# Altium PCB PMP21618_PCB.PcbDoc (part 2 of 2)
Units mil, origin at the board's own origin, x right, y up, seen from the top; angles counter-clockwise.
Board outline 4330 x 1770 mil, 4 copper layers (Top Layer, Signal Layer 1, Signal Layer 2, Bottom Layer), stack 136.834 mil thick; 75 components, 40 nets, 205 pads, 71 vias.
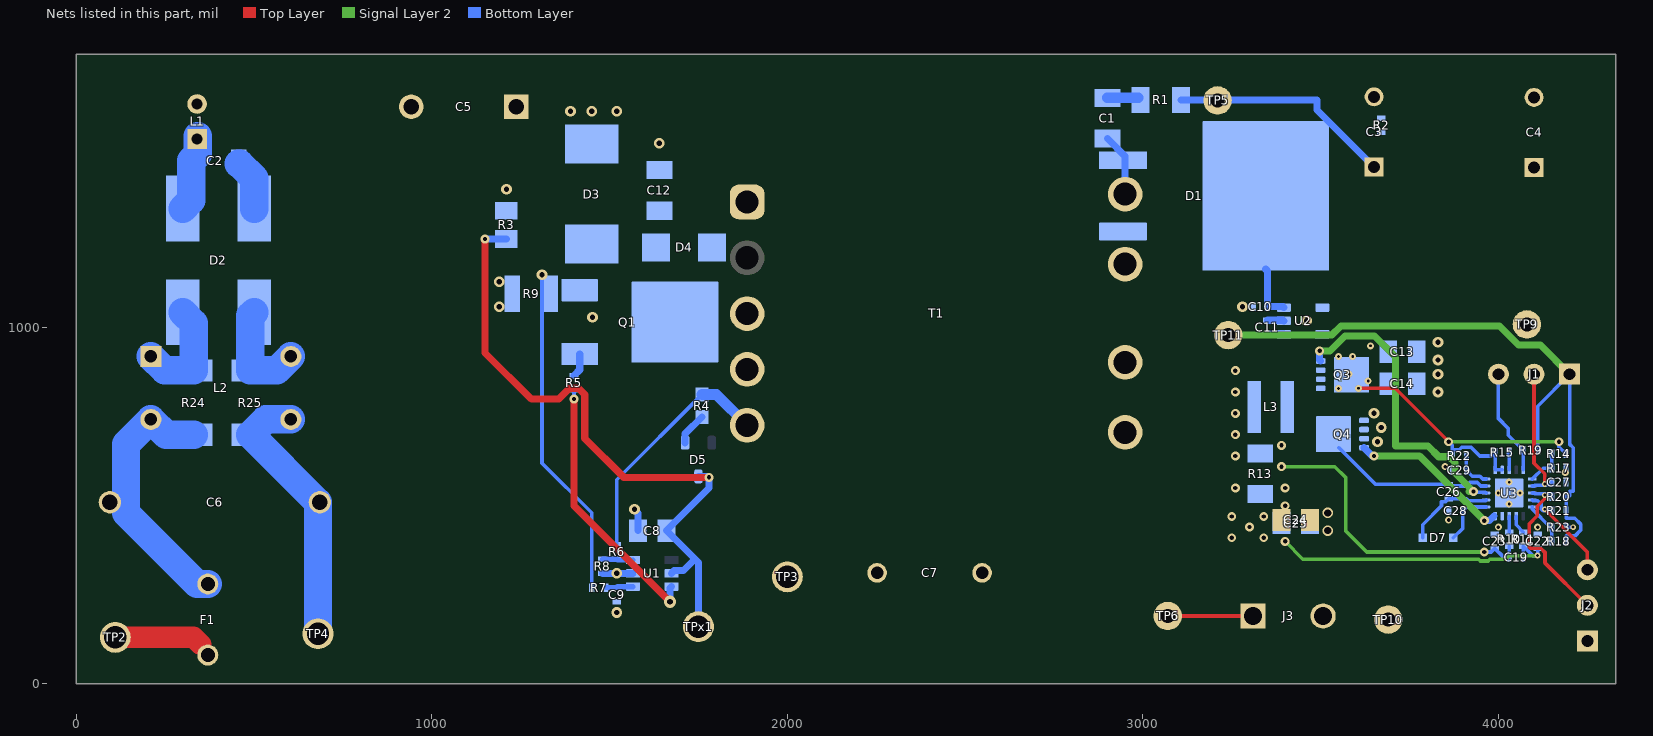
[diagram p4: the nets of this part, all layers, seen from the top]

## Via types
v1: diameter 25, hole 12, Top Layer to Bottom Layer, 26 vias
v2: diameter 30, hole 15, Top Layer to Bottom Layer, 21 vias
v3: diameter 19.68, hole 7.87, Top Layer to Bottom Layer, 10 vias
v4: diameter 16, hole 8, Top Layer to Bottom Layer, 5 vias
v5: diameter 20, hole 10, Top Layer to Bottom Layer, 5 vias
v6: diameter 30, hole 20, Top Layer to Bottom Layer, 2 vias
v7: diameter 34, hole 16, Top Layer to Bottom Layer, 1 vias
v8: diameter 19.68, hole 7.87, Top Layer to Bottom Layer, tented both sides, 1 vias

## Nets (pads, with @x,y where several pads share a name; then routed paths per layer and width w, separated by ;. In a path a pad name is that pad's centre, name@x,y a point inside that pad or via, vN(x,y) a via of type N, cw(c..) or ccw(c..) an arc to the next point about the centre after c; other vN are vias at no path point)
3v3: C11.1 J1.1 R18.2 R19.1 R20.1 R21.1 TP11.1 U2.1 | length 1991.7
  Signal Layer 2 w20: TP11.1@3240,980 3531.38,980 3556.97,1005.59 4002.56,1005.59 4056.03,952.13 4117.87,952.13 J1.1@4200,870
  Bottom Layer w10: TP11.1@3240,980 3348.5,980 C11.1@3350.31,981.81 ; R19.1@4110.16,655.91 4110.16,780.16 J1.1@4200,870 4200,673.77 4210.53,663.24 4210.53,603.81 4210.75,603.59 4210.75,541.25 4210.53,541.03 4200,541.03 4200,528.19 4197.72,525.91 R20.1@4190.16,525.91 R21.1@4190.16,485.91 4190.16,464.87 4214.65,464.87 4230.87,448.65 4230.87,430.87 4215.13,415.13 4190.16,415.13 4190.16,400.16 R18.2@4190,400
  Bottom Layer w20: C11.1@3350.31,981.81 3351.1,982.6 U2.1@3396.18,982.6
16VOUT: C3.1 C4.1 C10.1 C13.2 C14.2 D1.2 Q3.5 Q3.6 Q3.7 Q3.8 Q3.9 R1.2 R2.2 R14.2 R15.2 R22.1 TP5.1 U2.3 U3.1 U3.2 | length 1687.4
  Top Layer w10: v3(3606.29,830.31) 3709.69,830.31 v1(3860,680)
  Signal Layer 2 w10: v1(3860,680) v1(4170,680)
  Bottom Layer w10: v1(3860,680) 3870,670 3870,659.63 ; R22.1@3870,640 3870,659.63 ; U3.2@4010.47,600.87 U3.1@3990.79,600.87 3990.79,649.21 R15.2@3990,650 3980,640 3947.71,640 3922.83,664.87 3897.17,664.87 3889.63,657.33 3872.29,657.33 3870,659.63 ; v1(4170,680) 4170,666.06 R14.2@4190.16,645.91
  Bottom Layer w20: R1.2@3107.09,1641.49 3208.51,1641.49 TP5.1@3210,1640 3211.49,1641.49 3490,1641.49 3490,1613.07 C3.1@3631.57,1471.49 ; D1.2@3345.51,1165.23 3350,1160.74 C10.1@3350,1060 3393.58,1060 U2.3@3396.18,1057.4
  other v3: 3550,830 3633.7,851.21 3580,870 3550,920 3590,920
  other v8: 3640,950
ACOK: J1.3 R19.2 U3.5 | length 298.5
  Bottom Layer w10: J1.3@4000,870 4000,745.28 4027.87,717.4 4027.87,698.19 R19.2@4070.16,655.91 4069.53,655.28 U3.5@4069.53,600.87
GND: C3.2 C4.2 C7.1 C10.2 C11.2 C13.1 C14.1 C22.1 C23.1 C24.1 C25.1 C27.2 C28.2 C29.2 J2.1 J3.2 Q4.1 Q4.2 Q4.3 R2.1 R17.1 R23.1 T1.6 T1.7 TP9.1 TP10.1 U2.2 U2.4 U2.5 U3.14 U3.21 | length 59
  Bottom Layer w10: R23.1@4190,440 v4@4202.43,440
  Bottom Layer w20: C11.2@3350.31,1021.81 3394.37,1021.81 U2.2@3396.18,1020
  other v2: 3660,680 3670,720 3650,760 3830,820 3830,870 3830,910 3830,960 3460,1020 3280,1060
  other v3: 4030.16,505.39 3999.65,535.91 4060.67,535.91 4030.16,566.42
  other v4: 4210,440
  other v5: 4000,440 4110,440 3860,460 4187.87,594.11 3850,610
  other v6: 3520,430 3520,480
HIDRV: Q3.4 U3.18 | length 879
  Signal Layer 2 w20: v1(3497.04,935.63) 3526.43,935.63 3568.52,977.72 3651.48,977.72 3710,919.2 3710,667.87 3802.13,667.87 3832.13,637.87 3861.55,637.87 3877.87,621.55 3877.87,592.13 v1(3930,540) v1@3917.84,540
  Bottom Layer w10: v1(3930,540) 3932.28,537.72 3963.39,537.72 U3.18@3965.2,535.91
  Bottom Layer w20: Q3.4@3500,907.24 3497.04,910.19 v1(3497.04,935.63) v1@3500,932.67
IOUT: C27.1 J1.2 U3.7 | length 390.3
  Top Layer w10: J1.2@4100,870 4100,620 4130,590 v4(4130,561.2)
  Bottom Layer w10: U3.7@4095.12,555.59 4100.71,555.59 4102.8,557.68 v4@4126.48,557.68 ; v4(4130,561.2) v4@4126.48,557.68 ; C27.1@4150.16,565.91 4150.16,557.68 v4@4126.48,557.68
NetC1_1: C1.1 R1.1 | length 95.2
  Bottom Layer w10: R1.1@2987.32,1647.09 R1.1@2992.91,1641.49
  Bottom Layer w30: C1.1@2900,1647.09 R1.1@2987.32,1647.09
NetC1_2: C1.2 D1.1 D1.3 T1.8 T1.9 | length 177.1
  Bottom Layer w20: C1.2@2900,1532.91 2950,1482.92 T1.9@2950,1376.49
NetC2_1: C2.1 D2.1 L1.1 | length 221.7
  Bottom Layer w80: D2.1@299.61,1335.67 323.07,1359.13 C2.1@323.07,1470 341.57,1488.5 L1.1@341.57,1540
NetC5_1: C5.1 C12.1 D3.2 L1.2 R3.2 T1.1
  other v2: 1210,1390 1640,1520 1390,1610 1450,1610 1520,1610
NetC6_1: C6.1 F1.1 L2.2 R24.1 | length 742.6
  Bottom Layer w80: R24.1@330,699.45 253.39,699.45 L2.2@210,742.83 140,672.83 140,480 340,280 F1.1@370,280
NetC6_2: C6.2 L2.3 R25.1 TP4.1 | length 769.8
  Bottom Layer w80: L2.3@603.7,742.83 533.39,742.83 R25.1@490,699.45 680,509.45 TP4.1@680,140
NetC8_1: C8.1 D5.3 R3.1 TPx1.1 U1.2 | length 1872.7
  Top Layer w20: v1(1150,1250) 1150,930 1280,800 1357.04,800 1387.42,830.37 1412.58,830.37 1430.37,812.58 1430.37,689.63 1540,580 v1(1780,580)
  Bottom Layer w20: v1(1150,1250) R3.1@1210,1250 ; U1.2@1674.13,310 1681.85,317.72 1707.72,317.72 1740,350 ; TPx1.1@1750,160 1750,340 1740,350 ; D5.3@1750,582.76 1777.24,582.76 v1(1780,580) 1780,550 C8.1@1660,430 1740,350
NetC9_1: C9.1 R7.1 U1.4 | length 76.9
  Bottom Layer w15: R7.1@1490,270 C9.1@1520,270 1522.6,272.6 U1.4@1565.87,272.6
NetC12_2: C12.2 D3.1 D4.1
NetC19_1: C19.1 C22.2 C24.2 C25.2 J3.1 R11.2 R13.2 TP6.1 | length 1079.9
  Top Layer w10: TP6.1@3070,190 J3.1@3310,190
  Signal Layer 2 w10: v1(3400,400) 3450,350 3944.12,350 3949.49,344.63 3970.51,344.63 3975.88,350 4020,350 4030,360 v4(4110,360)
  Bottom Layer w10: C19.1@4070.16,355.91 R11.2@4070.16,385.91 4096.06,360 v4(4110,360) C22.2@4110,380
  other v1: 3250,410 3340,410 3300,440 3250,470 3340,470 3400,500 3260,550 3400,550
NetC19_2: C19.2 C23.2 L3.2 R10.2 R13.1 | length 871.6
  Signal Layer 2 w10: v1(3390,610) 3540,610 3570,580 3570,430 3630,370 v1(3960,370)
  Bottom Layer w10: v1(3960,370) 3980,370 C23.2@3990,380 4014.09,355.91 C19.2@4030.16,355.91 R10.2@4030.16,385.91
  other v1: 3260,640 3390,670 3260,700 3260,760 3260,820 3260,880
NetC26_1: C26.1 L3.1 Q3.1 Q3.2 Q3.3 Q4.5 Q4.6 Q4.7 Q4.8 Q4.9 U3.19 | length 466.5
  Bottom Layer w10: Q4.9@3551.38,663.23 3654.61,560 C26.1@3860,560 3864.41,555.59 3909.71,555.59 3919.49,565.37 3940.51,565.37 3950.29,555.59 U3.19@3965.2,555.59
NetC26_2: C26.2 D7.1 U3.17 | length 254.9
  Bottom Layer w10: D7.1@3786.69,410 3786.69,446.69 3839.78,499.78 3839.78,510.78 3850.78,510.78 C26.2@3860,520 3910,520 3915.37,514.63 3963.6,514.63 U3.17@3965.2,516.22
NetC28_1: C28.1 D7.2 U3.16 | length 156.5
  Bottom Layer w10: D7.2@3873.31,410 3900.16,436.85 C28.1@3900.16,485.91 3910.79,496.54 U3.16@3965.2,496.54
NetC29_1: C29.1 R22.2 U3.20 | length 105.4
  Bottom Layer w10: R22.2@3910,640 C29.1@3910,600 3926.75,583.25 3947.91,583.25 3955.89,575.28 U3.20@3965.2,575.28
NetD2_2: D2.2 L2.1 R24.2 | length 312.7
  Bottom Layer w80: L2.1@210,920 249.45,880.55 R24.2@330,880.55 330,1013.94 D2.2@299.61,1044.33
NetD2_3: D2.3 L2.4 R25.2 | length 298.1
  Bottom Layer w80: D2.3@500.39,1044.33 490,1033.94 R25.2@490,880.55 564.25,880.55 L2.4@603.7,920
NetD4_2: D4.2 Q1.2 T1.3
NetD5_1: D5.1 R4.1 | length 92.4
  Bottom Layer w20: D5.1@1712.6,677.24 1712.6,702.6 R4.1@1760,750
NetF1_2: F1.2 TP2.1 | length 248.3
  Top Layer w60: TP2.1@110,130 330,130 350,110
NetQ1_1: Q1.1 R5.2 | length 66.9
  Bottom Layer w20: R5.2@1400,866.49 1416.14,882.63 Q1.1@1416.14,926.73
NetQ1_3: Q1.3 R7.2 R9.2 | length 937.6
  Bottom Layer w10: v2(1310,1149.64) 1310,620 1450,480 R7.2@1450,270
  other v2: 1452.2,1030
NetQ4_4: Q4.4 U3.15 | length 456
  Signal Layer 2 w20: v1(3650,640) 3778.43,640 v1(3960.28,458.15)
  Bottom Layer w20: Q4.4@3622.05,663.07 3645.12,640 v1(3650,640) ; v1(3960.28,458.15) 3975.08,458.15 U3.15@3987.87,470.94
NetR4_2: R4.2 R6.2 T1.5 | length 685.2
  Bottom Layer w10: R6.2@1520,390 1520,572.99 R4.2@1760,812.99
  Bottom Layer w30: R4.2@1760,812.99 1800.5,812.99 T1.5@1887,726.49
NetR5_1: R5.1 U1.3 | length 752.6
  Top Layer w20: v1(1400,800) 1400,500 v7(1670,230)
  Bottom Layer w10: v1(1400,800) R5.1@1400,826.49
  Bottom Layer w20: v7(1670,230) 1670,268.46 U1.3@1674.13,272.6
NetR6_1: R6.1 R8.2 U1.6 | length 86.9
  Bottom Layer w15: R8.2@1480,350 R6.1@1520,350 1522.6,347.4 U1.6@1565.87,347.4
NetR10_1: R10.1 U3.13 | length 45
  Bottom Layer w10: R10.1@4030.16,425.91 U3.13@4030.16,470.94
NetR11_1: R11.1 U3.12 | length 53.5
  Bottom Layer w10: U3.12@4049.84,470.94 4049.84,446.22 R11.1@4070.16,425.91
NetR14_1: R14.1 R17.2 U3.6 | length 107.7
  Bottom Layer w10: U3.6@4095.12,575.28 4125.75,605.91 R17.2@4150.16,605.91 R14.1@4150.16,645.91
NetR15_1: R15.1 U3.3 | length 49.2
  Bottom Layer w10: R15.1@4030,650 4030.16,649.84 U3.3@4030.16,600.87
NetR18_1: R18.1 R23.2 U3.10 | length 121.6
  Bottom Layer w10: U3.10@4095.12,496.54 4095.12,490.94 4146.06,440 R23.2@4150,440 R18.1@4150,400
PGND: C2.2 C5.2 C7.2 C8.2 C9.2 D2.4 R8.1 R9.1 T1.4 TP3.1 U1.5 | length 295.9
  Bottom Layer w20: R8.1@1480,310 v2(1520,310) U1.5@1565.87,310 ; v2(1570,490) 1580,480 C8.2@1580,430
  Bottom Layer w80: C2.2@456.93,1462.13 459.37,1462.13 500.39,1421.1 D2.4@500.39,1335.67
  other v2: 1520,200 1190,1060 1190,1130
SCL: J2.3 R21.2 U3.9 | length 295.4
  Top Layer w10: v4(4130,490) 4250,370 J2.3@4250,320
  Bottom Layer w10: U3.9@4095.12,516.22 4096.93,514.41 4110.82,514.41 4119.8,505.43 4119.8,491.54 4125.43,485.91 R21.2@4150.16,485.91
SDA: J2.2 R20.2 U3.8 | length 481.6
  Top Layer w10: v4(4130,530) 4130,520 4120,510 4120,509.52 4109.13,498.65 4109.13,471.47 4087.13,449.47 4087.13,382.87 4089.13,380.87 4118.65,380.87 4130.87,368.65 4130.87,339.13 J2.2@4250,220
  Bottom Layer w10: U3.8@4095.12,535.91 4100.71,535.91 4102.8,533.82 v4@4126.48,533.82 ; v4(4130,530) 4130,530.3 v4@4126.48,533.82 ; R20.2@4150.16,525.91 4150.16,533.82 v4@4126.48,533.82
pads on no net: D5.2 Q3.9A Q3.9B Q3.9C Q3.9D Q4.9A Q4.9B Q4.9C Q4.9D T1.2 U1.1 U3.4 U3.11

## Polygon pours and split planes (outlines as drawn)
NetC5_1 on Bottom Layer "BOTTOM_LAYER_NETC5_1_P000" (solid, pour order 0): 240,1770 240,1600 700,1600 700,1300 2000,1300 2000,1770
NetD4_2 on Bottom Layer "BOTTOM_LAYER_NETD4_2_P004" (solid, pour order 4): 1510,880 1510,1160 1517.99,1167.99 1720,1167.99 1720,1285.39 1730,1295.39 1905.39,1120 1960,1120 1960,970 1830,970 1830,910 1800,880 1520,880
NetC12_2 on Bottom Layer "BOTTOM_LAYER_NETC12_2_P006" (solid, pour order 6): 1340,1166.04 1343.96,1170 1680,1170 1680,1363.74 1686.26,1370 1590,1370 1590,1296 1579,1284.99 1573.99,1290 1340,1290 1340,1170
NetQ1_3 on Bottom Layer "BOTTOM_LAYER_NETQ1_3_P008" (solid, pour order 8): 1490,1000 1490,1166.04 1486.04,1170 1280,1170 1280,1000
NetC1_2 on Bottom Layer "BOTTOM_LAYER_NETC1_2_P012" (solid, pour order 12): 2830,1520 3050,1520 3050,1100 2830,1100
16VOUT on Bottom Layer "BOTTOM_LAYER_16VOUT_P014" (solid, pour order 14): 3150,1100 4220,1100 4220,1580 3160,1580 3150,1590
16VOUT on Bottom Layer "BOTTOM_LAYER_16VOUT_P016" (solid, pour order 16): 3530,790 3720,790 3720,1120 3730,1130 3530,1130
NetC19_2 on Bottom Layer "BOTTOM_LAYER_NETC19_2_P020" (solid, pour order 20): 3240,900 3350,900 3350,682.52 3397.48,682.52 3400,680 3400,600 3240,600
NetC19_1 on Bottom Layer "BOTTOM_LAYER_NETC19_1_P022" (solid, pour order 22): 3240,570 3420,570 3420,0 3250,0 3240,-10
NetC26_1 on Bottom Layer "BOTTOM_LAYER_NETC26_1_P018" (solid, pour order 18): 3370,946.77 3520,946.77 3520,770 3590,770 3590,630 3600,620 3470,620 3470,700 3370,700
GND on Bottom Layer "BOTTOM_LAYER_GND_P046" (solid, pour order 46): 2461.49,1741.49 4331.49,1741.49 4331.49,1.49 2461.49,1.49
PGND on Bottom Layer "BOTTOM_LAYER_PGND_P038" (solid, pour order 38): 400,1220 400,1580 402.39,1577.61 700,1577.61 700,1770 2350,1770 2350,0 1310,0 1300,-10 1300,900 1120,900 1100,920 1100,1220
NetC5_1 on Top Layer "TOP_LAYER_NETC5_1_P002" (solid, pour order 2): 240,1770 240,1600 700,1600 700,1300 2000,1300 2000,1770
NetQ1_3 on Top Layer "TOP_LAYER_NETQ1_3_P010" (solid, pour order 10): 1495,1000 1495,1166.04 1491.04,1170 1285,1170 1285,1000
NetC19_1 on Top Layer "TOP_LAYER_NETC19_1_P026" (solid, pour order 26): 3240,570 3420,570 3420,0 3250,0 3240,-10
16VOUT on Top Layer "TOP_LAYER_16VOUT_P024" (solid, pour order 24): 3150,1100 4220,1100 4220,1580 3160,1580 3150,1590
16VOUT on Top Layer "TOP_LAYER_16VOUT_P028" (solid, pour order 28): 3530,790 3720,790 3720,1120 3730,1130 3530,1130
NetC19_2 on Top Layer "TOP_LAYER_NETC19_2_P030" (solid, pour order 30): 3240,900 3350,900 3350,682.52 3397.48,682.52 3400,680 3400,600 3240,600
GND on Top Layer "TOP_LAYER_GND_P040" (solid, pour order 40): 2460,1740 4330,1740 4330,0 2460,0
PGND on Top Layer "TOP_LAYER_PGND_P032" (solid, pour order 32): 400,1220 400,1580 402.39,1577.61 700,1577.61 700,1770 2350,1770 2350,0 1310,0 1300,-10 1300,900 1120,900 1100,920 1100,1220
GND on Signal Layer 1 "SIGNAL_LAYER_1_GND_P042" (solid, pour order 42): 2460.18,1739.88 4330.18,1739.88 4330.18,-0.12 2460.18,-0.12
PGND on Signal Layer 1 "SIGNAL_LAYER_1_PGND_P034" (solid, pour order 34): 400,1220 400,1580 402.39,1577.61 700,1577.61 700,1770 2350,1770 2350,0 1310,0 1300,-10 1300,900 1120,900 1100,920 1100,1220
GND on Signal Layer 2 "SIGNAL_LAYER_2_GND_P044" (solid, pour order 44): 2461.49,1741.49 4331.49,1741.49 4331.49,1.49 2461.49,1.49
PGND on Signal Layer 2 "SIGNAL_LAYER_2_PGND_P036" (solid, pour order 36): 400,1220 400,1580 402.39,1577.61 700,1577.61 700,1770 2350,1770 2350,0 1310,0 1300,-10 1300,900 1120,900 1100,920 1100,1220

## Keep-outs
Keep-Out Layer:
  text ".Layer_Name" at 577,-858.49 h60

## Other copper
Top Layer:
  text ".Layer_Name" at 577,-858.49 h60
Signal Layer 1:
  pour cut-out: 1510,880 1800,880 1830,910 1830,970 1970,970 1970,1130 1980,1140 1980,1160 1860,1160 1860,1280 1712.33,1280 1700,1267.67 1700,1170 1511.8,1170 1510,1171.8
Signal Layer 2:
  pour cut-out: 1510,880 1800,880 1830,910 1830,970 1970,970 1970,1130 1980,1140 1980,1160 1860,1160 1860,1280 1712.33,1280 1700,1267.67 1700,1170 1511.8,1170 1510,1171.8
Bottom Layer:
  text ".Layer_Name" at 577,-858.49 h60

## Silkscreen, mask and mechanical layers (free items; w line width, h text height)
Top Overlay:
  region: 2730,200 2430,200 2430,100 2730,100
  text "'.PRJ_Number'.PCB_Rev-" at 1845,125.77 h108.27
  text ".Layer_Name" at 577,-858.49 h60
Bottom Overlay:
  text ".Layer_Name" at 577,-858.49 h60
Top Paste:
  text ".Layer_Name" at 577,-858.49 h60
Bottom Paste:
  text ".Layer_Name" at 577,-858.49 h60
Top Solder:
  text ".Layer_Name" at 577,-858.49 h60
  text ".Layer_Name" at 577,-858.49 h60
Bottom Solder:
  text ".Layer_Name" at 577,-858.49 h60
Drill Guide:
  text ".Layer_Name" at 577,-858.49 h60
M1 Board Outline:
  text ".Layer_Name" at 577,-858.49 h60
M2 Board Dimensions:
  rectangle: 0,-275 125,-150
  rectangle: 125,-400 500,-275
  lines w7: 0,-275 1000,-275 ; 125,-400 125,-150 ; 250,-400 250,-150 ; 500,-400 500,-150 ; 750,-400 750,-150 ; 0,-400 1000,-400 1000,-150 0,-150 0,-400
  text ".Layer_Name" at 577,-858.49 h60
M3 3D STEP Top:
  text ".Layer_Name" at 577,-858.49 h60
M4 3D STEP Bottom:
  text ".Layer_Name" at 577,-858.49 h60
M5 Assembly Top:
  lines w10: -292,-930.17 6308,-930.17 ; -292,-726.83 6310,-726.83 ; -292,-523.5 -292,-1133.5 3713,-1133.5 6310,-1133.5 6310,-523.5 -291.5,-523.5 -291.5,-1133.5 1284,-1133.5 ; 2173,-1133.5 2173,-523.5 ; 3440,-726.83 3440,-523.5 ; 4280,-726.83 4280,-523.5 ; 4902,-1140 4902,-937.17
  text "COMPONENTS MARKED 'DNP' SHOULD NOT BE POPULATED." at 1153.5,-318.5 h60
  text "ASSEMBLY VARIANT:" at 1153,-434 h60
  text ".VariantName" at 2189,-434 h60
  text "PCB VIEWED FROM TOP SIDE" at -228.5,-655.67 h60
  text "BOARD #:" at 2248,-655.67 h60
  text ".PRJ_Number" at 2793.5,-655.67 h60
  text "REV:" at 3638,-655.67 h60
  text ".PCB_Rev" at 3929.5,-655.67 h60
  text "SVN REV:" at 4476,-655.67 h60
  text ".VersionControl_RevNumber" at 4982,-655.67 h60
  text "TID #:" at 2248,-859 h60
  text ".TID" at 2793.5,-859 h60
  text "PLOT NAME =" at -228.5,-1064.34 h60
  text ".plot_File_Name" at 577,-1064.34 h60
  text "GENERATED    :" at 2250,-1064.34 h60
  text ".Print_Date" at 3119.5,-1064.34 h60
  text ".Print_Time" at 3848.5,-1064.34 h60
  text "TEXAS INSTRUMENTS" at 5113,-1064.34 h60
M6 Assembly Bottom:
  lines w10: -292.5,-727.33 6309.5,-727.33 ; -290.5,-930.67 6309.5,-930.67 ; 1115.5,-1140.5 1115.5,-937.67 ; 1737.5,-727.33 1737.5,-524 ; 2577.5,-727.33 2577.5,-524 ; 3844.5,-1134 3844.5,-524 ; 4733.5,-1134 6309,-1134 6309,-524 -292.5,-524 -292.5,-1134 2304.5,-1134 6309.5,-1134 6309.5,-524
  text "COMPONENTS MARKED 'DNP' SHOULD NOT BE POPULATED." at 6102,-318 h60
  text ".VariantName" at 5058,-434 h60
  text "ASSEMBLY VARIANT:" at 6097,-434 h60
  text ".VersionControl_RevNumber" at 1035.5,-656.17 h60
  text "SVN REV:" at 1541.5,-656.17 h60
  text ".PCB_Rev" at 2088,-656.17 h60
  text "REV:" at 2379.5,-656.17 h60
  text ".PRJ_Number" at 3224,-656.17 h60
  text "BOARD #:" at 3769.5,-656.17 h60
  text "PCB VIEWED FROM BOTTOM SIDE" at 6246,-656.17 h60
  text ".TID" at 3224,-859.5 h60
  text "TID #:" at 3769.5,-859.5 h60
  text "TEXAS INSTRUMENTS" at 904.5,-1064.84 h60
  text ".Print_Time" at 2169,-1064.84 h60
  text ".Print_Date" at 2898,-1064.84 h60
  text "GENERATED    :" at 3767.5,-1064.84 h60
  text ".plot_File_Name" at 5440.5,-1064.84 h60
  text "PLOT NAME =" at 6246,-1064.84 h60
M9 Title Sheet:
  drawing of 57 lines, arcs and shapes, not listed
  text "1" at 739.84,8036.5 h70
  text "2" at 3235.5,8036.5 h70
  text "3" at 5724.84,8036.5 h70
  text "4" at 8231.51,8036.5 h70
  text "5" at 10730.5,8036.5 h70
  text "6" at 13235.5,8036.5 h70
  text "A" at -416.5,6893.5 h70
  text "A" at 14383.5,6893.5 h70
  text "B" at -416.5,4513.5 h70
  text "B" at 14383.5,4513.5 h70
  text "C" at -416.5,2138.5 h70
  text "C" at 14383.5,2138.5 h70
  text "PROJECT TITLE:" at 11343.5,277.5 h45
  text ".PRJ_Title" at 11393.5,144.17 h70
  text "DESIGNED FOR:" at 11343.5,-23.5 h45
  text ".PRJ_Customer" at 11393.5,-163.5 h70
  text "D" at -416.5,-231.5 h70
  text "D" at 14383.5,-231.5 h70
  text "FILE NAME:" at 11343.5,-323.5 h45
  text ".PCB_File_Name_No_Path" at 11393.5,-443.5 h70
  text "Texas Instruments (TI) and/or its licensors do not warrant the accuracy or completeness of this specification" at 6374,-605.34 h45
  text "ENGINEER:" at 11343.5,-613.5 h45
  text "LAYOUT BY:" at 12848.5,-613.5 h45
  text "or any information contained therein. TI and/or its licensors do not warrant that this design will meet" at 6329.01,-718 h45
  text ".PRJ_Engineer" at 11393.5,-768.49 h70
  text ".PCB_Layout" at 12899,-768.49 h70
  text "the specifications, will be suitable for your application or fit for any particular purpose, or will operate in" at 6329.01,-830.67 h45
  text ".Layer_Name" at 577,-858.49 h60
  text "ALTIUM DESIGNER VERSION:" at 12848.5,-923.5 h45
  text "an implementation. TI and/or its licensors do not warrant that the design is production worthy. You should" at 6329.01,-943.33 h45
  text "completely validate and test your design implementation to confirm the system functionality for your application." at 6374,-1056 h45
  text ".print_Scale" at 11393.5,-1056.83 h70
  text ".Application_BuildNumber" at 12899,-1056.83 h70
  text "1" at 739.84,-1263.5 h70
  text "2" at 3235.5,-1263.5 h70
  text "3" at 5724.84,-1263.5 h70
  text "4" at 8231.51,-1263.5 h70
  text "5" at 10730.5,-1263.5 h70
  text "6" at 13235.5,-1263.5 h70
M10 Fab Notes:
  drawing of 189 lines, arcs and shapes, not listed
  text "DESIGN INFORMATION" at 12382.02,6356.17 h60
  text "MIN. TRACK WIDTH:" at 11737.46,6224.05 h60
  text "8" at 12833.7,6224.05 h60
  text "MIL" at 12988.46,6224.05 h60
  text "MIN. CLEARANCE:" at 11737.46,6099.92 h60
  text "0.2" at 12773.7,6099.93 h60
  text "mm" at 12988.46,6099.92 h60
  text "MIN. VIA PAD SIZE:" at 11737.46,5975.8 h60
  text "24" at 12803.71,5975.8 h60
  text "MIL" at 12988.46,5975.8 h60
  text "0.05mm (2MIL)" at 12432.46,5845.9 h60
  text "MINIMUM ANNULAR RING" at 11408.23,5837.67 h60
  text "EXTERNAL" at 13140.46,5837.67 h60
  text "PER" at 11608.23,5727.55 h60
  text "IPC-D-275 CLASS 2 LEVEL C" at 11828.23,5727.54 h60
  text "MIL, HOLES" at 13316.46,5627.07 h60
  text "+/-" at 12924,5618.48 h60
  text "+/-" at 13778,5618.48 h60
  text "REGISTRATION TOLERANCES:" at 11408.23,5617.42 h60
  text "METAL" at 12608,5617.42 h60
  text "5" at 13184.2,5617.42 h60
  text "3" at 14017.2,5617.42 h60
  text "MIL" at 14133.46,5617.42 h60
  text "HOLE SIZE TOLERANCE (UNLESS OTHERWISE SPECIFIED):" at 11408.23,5519.1 h60
  text "+/-" at 13778,5516.23 h60
  text "3" at 14017.2,5515.17 h60
  text "MIL" at 14133.46,5515.17 h60
  text "MATERIAL:" at 11333.46,5377.52 h60
  text "FR-4 High Tg" at 12319.9,5249 h60
  text "X" at 12175.46,5241.01 h60
  text "FR-408" at 11754.46,5236.49 h60
  text "OTHER" at 13242.46,5236.49 h60
  text "62 MIL (1.6mm) +/-10%" at 12074.56,5093.46 h60
  text "X" at 11954.46,5091.01 h60
  text "THICKNESS:" at 11408.23,5085.24 h60
  text "OTHER" at 13359.46,5085.24 h60
  text "TOLERANCE:" at 11408.23,4946.92 h60
  text "X" at 12256.46,4946.92 h60
  text "ANSI IPC-6012 TYPE 3 CLASS 2" at 12434.48,4946.92 h60
  text "OTHER +/-" at 12434.46,4802.73 h60
  text "BOW & TWIST:" at 11408.23,4657.54 h60
  text "X" at 12256.46,4657.54 h60
  text "ANSI IPC-6012 TYPE 3 CLASS 2" at 12434.48,4657.54 h60
  text "OTHER +/-" at 12434.46,4510.85 h60
  text "DRILLING:" at 11333.46,4380.23 h60
  text "NC_DRILL FILES" at 13094.46,4275.04 h60
  text "REFERENCE:" at 11408.23,4271.1 h60
  text "X" at 12065.46,4271.01 h60
  text "AS SHOWN" at 12243.46,4271.1 h60
  text "X" at 12966.46,4271.1 h60
  text "OTHER" at 13392.46,4128.85 h60
  text "PTH COPPER THICKNESS:" at 11407.91,4125.32 h60
  text "X" at 12547.14,4125.32 h60
  text "20-30 um" at 12675.14,4125.32 h60
  text "BOARD FINISH:" at 11333.46,3977.73 h60
  text "SILKSCREEN:" at 11488.68,3867.6 h60
  text "X" at 12446.46,3867.6 h60
  text "TOP" at 12563.46,3867.6 h60
  text "X" at 12956.46,3867.6 h60
  text "BOTTOM" at 13074.46,3867.6 h60
  text "SILKSCREEN COLOR:" at 11488.68,3712.41 h60
  text "X" at 12445.46,3712.41 h60
  text "WHITE" at 12563.46,3712.41 h60
  text "OTHER" at 13074.46,3712.41 h60
  text "X" at 12576.46,3568.96 h60
  text "GREEN" at 12694.46,3568.96 h60
  text "OTHER" at 13312.46,3568.96 h60
  text "SOLDER RESIST COLOR:" at 11488.68,3562.1 h60
  text "X" at 12576.46,3414.71 h60
  text "MATTE" at 12694.46,3414.71 h60
  text "SEMI-GLOSS" at 13312,3414.07 h60
  text "IMMERSION GOLD (ENIG)" at 12394.46,3241.94 h60
  text "ENEPIG" at 13732,3234.72 h60
  text "SURFACE FINISH:" at 11333.46,3233.72 h60
  text "X" at 12216.46,3233.72 h60
  text "IMM. TIN/SILVER OR EQUIV" at 11663,3096.4 h60
  text "OTHER" at 13094.46,3092.47 h60
  text "ARRAY/PANEL:" at 11333.46,2937.09 h60
  text "CUT AND TRIM PER M1 BOARD OUTLINE" at 12394.46,2928.87 h60
  text "N.C. ROUTE" at 12394.46,2792.9 h60
  text "X" at 13082.46,2792.9 h60
  text "V. SCORE" at 13260.46,2792.9 h60
  text "CERTIFICATION:" at 11333.46,2663.77 h60
  text "MATERIALS AND WORKMANSHIP FOR ALL PCBS" at 12058.46,2663.77 h60
  text "TO MEET OR EXCEED THE REQUIREMENTS OF:" at 12058.46,2569.71 h60
  text "X" at 11695.97,2441.08 h60
  text "ANSI IPC-A-600F CLASS ->" at 11823.96,2441.08 h60
  text "X" at 13471.97,2441.08 h60
  text "2" at 13581.96,2441.08 h60
  text "1" at 13266.96,2439.58 h60
  text "3" at 13935.96,2439.58 h60
  text "X" at 12507.97,2293.39 h60
  text "RoHS" at 12635.96,2293.39 h60
  text "OTHER" at 13280.36,2293.39 h60
  text "PER ORDER" at 13677.42,2293.39 h60
  text "ALL BOARDS MUST MEET OR EXCEED UL94-V0 REQUIREMENTS." at 11361,2139.57 h60
  text "PCB MUST BEAR THE UL94V-0 UL REGISTERED MATERIAL ID NUMBER" at 11361,2023.5 h60
  text "ADDITIONAL REQUIREMENTS:" at 11333.46,1854.08 h60
  text "MICROSECTION:" at 11408.23,1746.95 h60
  text "YES" at 12313.96,1746.95 h60
  text "REQUIRED" at 13175.46,1602.62 h60
  text "BARE BOARD ELEC. TEST:" at 11408.23,1599.76 h60
  text "NONE" at 12713.96,1599.76 h60
  text "X" at 13057.46,1599.76 h60
  text "PER ORDER" at 13767.46,1599.76 h60
  text "XX MIL VIAS REQUIRE NON-CONDUCTIVE FILL AND PLANARIZE" at 11576.38,1394.82 h59
  text "XX MIL VIAS REQUIRE CONDUCTIVE FILL AND PLANARIZE" at 11584.38,1290.84 h60
  text "OUTER XX MIL VIAS REQUIRE 50 OHM SINGLE-ENDED IMPEDANCE" at 11583.39,1127.46 h58
  text "LAYER 2 & 3 (INNER LAYERS) XX MIL WIDE, XX MIL SPACE / TRACES REQUIRE 100 OHM DIFFERENTIAL IMPEDANCE" at 11575.39,891.74 h60
  text ".Layer_Name" at 577,-858.49 h60
M11 Gerber Information:
  lines w10: -292,-930.17 6308,-930.17 ; -292,-726.83 6310,-726.83 ; -292,-523.5 -292,-1133.5 3713,-1133.5 6310,-1133.5 6310,-523.5 -291.5,-523.5 -291.5,-1133.5 1284,-1133.5 ; 2173,-1133.5 2173,-523.5 ; 3440,-726.83 3440,-523.5 ; 4280,-726.83 4280,-523.5 ; 4902,-1140 4902,-937.17
  text "ALL ARTWORK VIEWED FROM TOP SIDE" at -228.5,-655.67 h60
  text "BOARD #:" at 2248,-655.67 h60
  text ".PRJ_Number" at 2793.5,-655.67 h60
  text "REV:" at 3638,-655.67 h60
  text ".PCB_Rev" at 3929.5,-655.67 h60
  text "SVN REV:" at 4476,-655.67 h60
  text ".VersionControl_RevNumber" at 4982,-655.67 h60
  text "LAYER NAME =" at -228.5,-858.49 h60
  text "TID #:" at 2248,-859 h60
  text ".TID" at 2793.5,-859 h60
  text "PLOT NAME =" at -228.5,-1064.34 h60
  text ".plot_File_Name" at 577,-1064.34 h60
  text "GENERATED    :" at 2250,-1064.34 h60
  text ".Print_Date" at 3119.5,-1064.34 h60
  text ".Print_Time" at 3848.5,-1064.34 h60
  text "TEXAS INSTRUMENTS" at 5113,-1064.34 h60
M12 Stackup:
  drawing of 295 lines, arcs and shapes, not listed
  text "Layer" at 9797.84,7830 h60
  text "Name" at 10207.76,7830 h60
  text "Material" at 11147.5,7830 h60
  text "Thickness" at 12007.26,7830 h60
  text "Constant" at 12657.1,7830 h60
  text "Board Layer Stack" at 13226.96,7830 h60
  text "1" at 9797.84,7710 h60
  text "Top Overlay" at 10207.76,7710 h60
  text "2" at 9797.84,7590 h60
  text "Top Solder" at 10207.76,7590 h60
  text "Solder Resist" at 11147.5,7590 h60
  text "0.40mil" at 12007.26,7590 h60
  text "3.5" at 12657.1,7590 h60
  text "3" at 9797.84,7470 h60
  text "Top Layer" at 10207.76,7470 h60
  text "Copper" at 11147.5,7470 h60
  text "2.80mil" at 12007.26,7470 h60
  text "4" at 9797.84,7350 h60
  text "Dielectric1" at 10207.76,7350 h60
  text "FR-4" at 11147.5,7350 h60
  text "59.20mil" at 12007.26,7350 h60
  text "4.8" at 12657.1,7350 h60
  text "5" at 9797.84,7230 h60
  text "Signal Layer 1" at 10207.76,7230 h60
  text "Copper" at 11147.5,7230 h60
  text "1.42mil" at 12007.26,7230 h60
  text "6" at 9797.84,7110 h60
  text "Dielectric 3" at 10207.76,7110 h60
  text "FR-4" at 11147.5,7110 h60
  text "59.20mil" at 12007.26,7110 h60
  text "4.8" at 12657.1,7110 h60
  text "7" at 9797.84,6990 h60
  text "Signal Layer 2" at 10207.76,6990 h60
  text "Copper" at 11147.5,6990 h60
  text "1.42mil" at 12007.26,6990 h60
  text "8" at 9797.84,6870 h60
  text "Dielectric 2" at 10207.76,6870 h60
  text "FR-4" at 11147.5,6870 h60
  text "10.00mil" at 12007.26,6870 h60
  text "4.8" at 12657.1,6870 h60
  text "9" at 9797.84,6750 h60
  text "Bottom Layer" at 10207.76,6750 h60
  text "Copper" at 11147.5,6750 h60
  text "2.80mil" at 12007.26,6750 h60
  text "10" at 9797.84,6630 h60
  text "Bottom Solder" at 10207.76,6630 h60
  text "Solder Resist" at 11147.5,6630 h60
  text "0.40mil" at 12007.26,6630 h60
  text "3.5" at 12657.1,6630 h60
  text "11" at 9797.84,6510 h60
  text "Bottom Overlay" at 10207.76,6510 h60
  text ".Layer_Name" at 577,-858.49 h60
M13 Component Bodies Top:
  text ".Layer_Name" at 577,-858.49 h60
M14 Component Bodies Bottom:
  text ".Layer_Name" at 577,-858.49 h60
M15 Courtyards Top:
  text ".Layer_Name" at 577,-858.49 h60
M16 Courtyards Bottom:
  text ".Layer_Name" at 577,-858.49 h60
Drill Drawing:
  drawing of 184 lines, arcs and shapes, not listed
  text "Symbol" at 5360.59,3362.98 h72
  text "Quantity" at 5661.16,3362.98 h72
  text "Finished Hole Size" at 5993.16,3362.98 h72
  text "Plated" at 6629.72,3362.98 h72
  text "Hole Type" at 6888.86,3362.98 h72
  text "Drill Layer Pair" at 7264.02,3362.98 h72
  text "Hole Tolerance" at 7988.35,3362.98 h72
  text "11" at 5661.16,3238.66 h60
  text "7.87mil (0.200mm)" at 5993.16,3238.66 h60
  text "PTH" at 6629.72,3238.66 h60
  text "Round" at 6888.86,3238.66 h60
  text "Top Layer - Bottom Layer" at 7264.02,3238.66 h60
  text "5" at 5661.16,3114.34 h60
  text "8.00mil (0.203mm)" at 5993.16,3114.34 h60
  text "PTH" at 6629.72,3114.34 h60
  text "Round" at 6888.86,3114.34 h60
  text "Top Layer - Bottom Layer" at 7264.02,3114.34 h60
  text "5" at 5661.16,2990.02 h60
  text "10.00mil (0.254mm)" at 5993.16,2990.02 h60
  text "PTH" at 6629.72,2990.02 h60
  text "Round" at 6888.86,2990.02 h60
  text "Top Layer - Bottom Layer" at 7264.02,2990.02 h60
  text "A" at 5335.31,2980.02 h55.25
  text "26" at 5661.16,2865.7 h60
  text "12.00mil (0.305mm)" at 5993.16,2865.7 h60
  text "PTH" at 6629.72,2865.7 h60
  text "Round" at 6888.86,2865.7 h60
  text "Top Layer - Bottom Layer" at 7264.02,2865.7 h60
  text "21" at 5661.16,2741.38 h60
  text "15.00mil (0.381mm)" at 5993.16,2741.38 h60
  text "PTH" at 6629.72,2741.38 h60
  text "Round" at 6888.86,2741.38 h60
  text "Top Layer - Bottom Layer" at 7264.02,2741.38 h60
  text "1" at 5661.16,2617.06 h60
  text "16.00mil (0.406mm)" at 5993.16,2617.06 h60
  text "PTH" at 6629.72,2617.06 h60
  text "Round" at 6888.86,2617.06 h60
  text "Top Layer - Bottom Layer" at 7264.02,2617.06 h60
  text "2" at 5661.16,2492.74 h60
  text "20.00mil (0.508mm)" at 5993.16,2492.74 h60
  text "PTH" at 6629.72,2492.74 h60
  text "Round" at 6888.86,2492.74 h60
  text "Top Layer - Bottom Layer" at 7264.02,2492.74 h60
  text "2" at 5661.16,2368.42 h60
  text "31.00mil (0.787mm)" at 5993.16,2368.42 h60
  text "PTH" at 6629.72,2368.42 h60
  text "Round" at 6888.86,2368.42 h60
  text "Top Layer - Bottom Layer" at 7264.02,2368.42 h60
  text "10" at 5661.16,2244.1 h60
  text "33.47mil (0.850mm)" at 5993.16,2244.1 h60
  text "PTH" at 6629.72,2244.1 h60
  text "Round" at 6888.86,2244.1 h60
  text "Top Layer - Bottom Layer" at 7264.02,2244.1 h60
  text "6" at 5661.16,2119.78 h60
  text "35.43mil (0.900mm)" at 5993.16,2119.78 h60
  text "PTH" at 6629.72,2119.78 h60
  text "Round" at 6888.86,2119.78 h60
  text "Top Layer - Bottom Layer" at 7264.02,2119.78 h60
  text "2" at 5661.16,1995.46 h60
  text "39.37mil (1.000mm)" at 5993.16,1995.46 h60
  text "PTH" at 6629.72,1995.46 h60
  text "Round" at 6888.86,1995.46 h60
  text "Top Layer - Bottom Layer" at 7264.02,1995.46 h60
  text "5" at 5661.16,1871.14 h60
  text "40.00mil (1.016mm)" at 5993.16,1871.14 h60
  text "PTH" at 6629.72,1871.14 h60
  text "Round" at 6888.86,1871.14 h60
  text "Top Layer - Bottom Layer" at 7264.02,1871.14 h60
  text "4" at 5661.16,1746.82 h60
  text "43.31mil (1.100mm)" at 5993.16,1746.82 h60
  text "PTH" at 6629.72,1746.82 h60
  text "Round" at 6888.86,1746.82 h60
  text "Top Layer - Bottom Layer" at 7264.02,1746.82 h60
  text "2" at 5661.16,1622.5 h60
  text "51.18mil (1.300mm)" at 5993.16,1622.5 h60
  text "PTH" at 6629.72,1622.5 h60
  text "Round" at 6888.86,1622.5 h60
  text "Top Layer - Bottom Layer" at 7264.02,1622.5 h60
  text "4" at 5661.16,1498.18 h60
  text "63.00mil (1.600mm)" at 5993.16,1498.18 h60
  text "PTH" at 6629.72,1498.18 h60
  text "Round" at 6888.86,1498.18 h60
  text "Top Layer - Bottom Layer" at 7264.02,1498.18 h60
  text "9" at 5661.16,1373.86 h60
  text "64.96mil (1.650mm)" at 5993.16,1373.86 h60
  text "PTH" at 6629.72,1373.86 h60
  text "Round" at 6888.86,1373.86 h60
  text "Top Layer - Bottom Layer" at 7264.02,1373.86 h60
  text "115 Total" at 5661.16,1249.54 h60
  text ".Layer_Name" at 577,-858.49 h60
M17 Embedded Cavity:
  text ".Layer_Name" at 577,-858.49 h60
M18 Embedded Assembly:
  text ".Layer_Name" at 577,-858.49 h60
M19 Embedded Keepout:
  text ".Layer_Name" at 577,-858.49 h60

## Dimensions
0,-400 to 1000,-400 on M2 Board Dimensions
0,0 to 0,1770 on M2 Board Dimensions
0,0 to 4330,0 on M2 Board Dimensions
